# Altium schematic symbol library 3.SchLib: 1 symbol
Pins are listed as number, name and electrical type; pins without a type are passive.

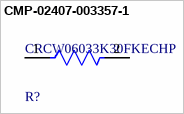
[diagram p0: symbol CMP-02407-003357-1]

## CMP-02407-003357-1
designator R?, comment CRCW06033K30FKECHP
RES Thick Film, 3.3kΩ, 1%, 0.33W, 100ppm/°C, 0603; Power Rating: 100mW; Resistance: 3.3kR
footprint FP-CRCW0603-HPe3-IPC_B
footprint FP-CRCW0603-HPe3-MFG
footprint FP-CRCW0603-HPe3-IPC_C
footprint FP-CRCW0603-HPe3-IPC_A
pins: 1, 2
